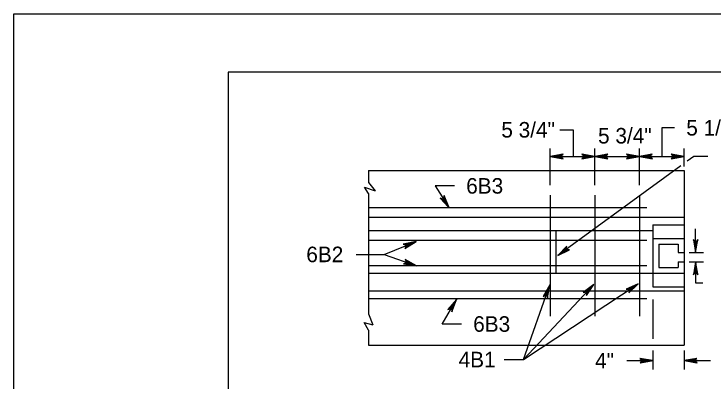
# Model space of a CAD drawing. Extents: x 499866 to 500993, y 499985 to 500645.
# Drawn here: x 499944.8 to 500124.8, y 500550.5 to 500645 of the extents above; entities that cross this region are included whole.
import ezdxf

# ---------------------------------------------------------------- set-up
doc = ezdxf.new("R2010")
doc.units = 0
for name, color, linetype in [('1', 7, 'Continuous'), ('24', 7, 'Continuous'), ('41', 7, 'Continuous'), ('5', 7, 'Continuous')]:
    doc.layers.add(name, color=color, linetype=linetype)

msp = doc.modelspace()

# ---------------------------------------------------------------- linework, layer by layer
at = {"layer": '1'}
for p, q in [((499944.83, 500645), (500993, 500645)), ((500000, 500630), (500000, 500000)), ((500990, 500630), (500000, 500630))]:
    msp.add_line(p, q, dxfattribs=at)
at = {"layer": '24'}
for points in [[(500082.83, 500608.32), (500086.18, 500607.73), (500085.38, 500608.32), (500086.16, 500608.9), (500082.83, 500608.32), (500083.05, 500608.33), (500086.09, 500607.77), (500085.32, 500608.33), (500086.03, 500608.86), (500083.17, 500608.34), (500083.29, 500608.32), (500085.88, 500607.86), (500085.3, 500608.33), (500085.9, 500608.78), (500083.34, 500608.32), (500083.45, 500608.34), (500085.72, 500607.93), (500085.28, 500608.32), (500085.73, 500608.73), (500083.77, 500608.34), (500083.96, 500608.34), (500085.55, 500608.01), (500085.24, 500608.31), (500085.57, 500608.64), (500083.99, 500608.32), (500084.17, 500608.31), (500085.37, 500608.11), (500085.14, 500608.34), (500085.39, 500608.57), (500084.34, 500608.32), (500084.51, 500608.3), (500085.22, 500608.17), (500085.11, 500608.33), (500085.3, 500608.51), (500084.59, 500608.32), (500085.06, 500608.21), (500084.99, 500608.34), (500085.2, 500608.47), (500084.71, 500608.34), (500085.02, 500608.26), (500084.89, 500608.36), (500085.04, 500608.42), (500084.89, 500608.33), (500084.97, 500608.31)], [(500094.32, 500608.32), (500090.97, 500608.91), (500091.77, 500608.32), (500090.99, 500607.74), (500094.32, 500608.32), (500094.1, 500608.31), (500091.07, 500608.87), (500091.84, 500608.31), (500091.12, 500607.78), (500093.98, 500608.3), (500093.87, 500608.32), (500091.27, 500608.78), (500091.85, 500608.31), (500091.25, 500607.86), (500093.82, 500608.32), (500093.71, 500608.3), (500091.43, 500608.71), (500091.88, 500608.32), (500091.43, 500607.91), (500093.38, 500608.3), (500093.19, 500608.3), (500091.6, 500608.63), (500091.91, 500608.33), (500091.58, 500608), (500093.16, 500608.32), (500092.98, 500608.33), (500091.79, 500608.54), (500092.02, 500608.3), (500091.77, 500608.07), (500092.82, 500608.32), (500092.65, 500608.34), (500091.93, 500608.47), (500092.05, 500608.31), (500091.85, 500608.13), (500092.56, 500608.32), (500092.09, 500608.43), (500092.16, 500608.3), (500091.95, 500608.18), (500092.44, 500608.3), (500092.14, 500608.38), (500092.26, 500608.28), (500092.12, 500608.22), (500092.26, 500608.31), (500092.19, 500608.33)], [(500094.32, 500608.32), (500097.67, 500607.73), (500096.87, 500608.32), (500097.66, 500608.9), (500094.32, 500608.32), (500094.54, 500608.33), (500097.58, 500607.77), (500096.81, 500608.33), (500097.52, 500608.86), (500094.67, 500608.34), (500094.78, 500608.32), (500097.38, 500607.86), (500096.79, 500608.33), (500097.39, 500608.78), (500094.83, 500608.32), (500094.94, 500608.34), (500097.21, 500607.93), (500096.77, 500608.32), (500097.22, 500608.73), (500095.26, 500608.34), (500095.45, 500608.34), (500097.04, 500608.01), (500096.73, 500608.31), (500097.07, 500608.64), (500095.49, 500608.32), (500095.66, 500608.31), (500096.86, 500608.11), (500096.63, 500608.34), (500096.88, 500608.57), (500095.83, 500608.32), (500096, 500608.3), (500096.72, 500608.17), (500096.6, 500608.33), (500096.79, 500608.51), (500096.08, 500608.32), (500096.55, 500608.21), (500096.49, 500608.34), (500096.69, 500608.47), (500096.2, 500608.34), (500096.51, 500608.26), (500096.38, 500608.36), (500096.53, 500608.42), (500096.38, 500608.33), (500096.46, 500608.31)], [(500105.81, 500608.32), (500102.46, 500608.91), (500103.26, 500608.32), (500102.48, 500607.74), (500105.81, 500608.32), (500105.59, 500608.31), (500102.56, 500608.87), (500103.33, 500608.31), (500102.62, 500607.78), (500105.47, 500608.3), (500105.36, 500608.32), (500102.76, 500608.78), (500103.34, 500608.31), (500102.74, 500607.86), (500105.31, 500608.32), (500105.2, 500608.3), (500102.93, 500608.71), (500103.37, 500608.32), (500102.92, 500607.91), (500104.87, 500608.3), (500104.69, 500608.3), (500103.09, 500608.63), (500103.4, 500608.33), (500103.07, 500608), (500104.65, 500608.32), (500104.47, 500608.33), (500103.28, 500608.54), (500103.51, 500608.3), (500103.26, 500608.07), (500104.31, 500608.32), (500104.14, 500608.34), (500103.42, 500608.47), (500103.54, 500608.31), (500103.34, 500608.13), (500104.05, 500608.32), (500103.58, 500608.43), (500103.65, 500608.3), (500103.45, 500608.18), (500103.93, 500608.3), (500103.63, 500608.38), (500103.76, 500608.28), (500103.61, 500608.22), (500103.75, 500608.31), (500103.68, 500608.33)], [(500105.81, 500608.32), (500109.16, 500607.73), (500108.36, 500608.32), (500109.15, 500608.9), (500105.81, 500608.32), (500106.04, 500608.33), (500109.07, 500607.77), (500108.3, 500608.33), (500109.01, 500608.86), (500106.16, 500608.34), (500106.27, 500608.32), (500108.87, 500607.86), (500108.28, 500608.33), (500108.88, 500608.78), (500106.32, 500608.32), (500106.43, 500608.34), (500108.7, 500607.93), (500108.26, 500608.32), (500108.71, 500608.73), (500106.75, 500608.34), (500106.94, 500608.34), (500108.53, 500608.01), (500108.22, 500608.31), (500108.56, 500608.64), (500106.98, 500608.32), (500107.16, 500608.31), (500108.35, 500608.11), (500108.12, 500608.34), (500108.37, 500608.57), (500107.32, 500608.32), (500107.49, 500608.3), (500108.21, 500608.17), (500108.09, 500608.33), (500108.28, 500608.51), (500107.58, 500608.32), (500108.04, 500608.21), (500107.98, 500608.34), (500108.18, 500608.47), (500107.69, 500608.34), (500108, 500608.26), (500107.87, 500608.36), (500108.02, 500608.42), (500107.87, 500608.33), (500107.95, 500608.31)], [(500117.31, 500608.32), (500113.96, 500608.91), (500114.76, 500608.32), (500113.97, 500607.74), (500117.31, 500608.32), (500117.08, 500608.31), (500114.05, 500608.87), (500114.82, 500608.31), (500114.11, 500607.78), (500116.96, 500608.3), (500116.85, 500608.32), (500114.25, 500608.78), (500114.84, 500608.31), (500114.24, 500607.86), (500116.8, 500608.32), (500116.69, 500608.3), (500114.42, 500608.71), (500114.86, 500608.32), (500114.41, 500607.91), (500116.37, 500608.3), (500116.18, 500608.3), (500114.59, 500608.63), (500114.9, 500608.33), (500114.56, 500608), (500116.14, 500608.32), (500115.96, 500608.33), (500114.77, 500608.54), (500115, 500608.3), (500114.75, 500608.07), (500115.8, 500608.32), (500115.63, 500608.34), (500114.91, 500608.47), (500115.03, 500608.31), (500114.83, 500608.13), (500115.54, 500608.32), (500115.07, 500608.43), (500115.14, 500608.3), (500114.94, 500608.18), (500115.43, 500608.3), (500115.12, 500608.38), (500115.25, 500608.28), (500115.1, 500608.22), (500115.25, 500608.31), (500115.17, 500608.33)], [(500056.82, 500595.07), (500055.54, 500598.22), (500055.46, 500597.23), (500054.55, 500597.58), (500056.82, 500595.07), (500056.7, 500595.26), (500055.55, 500598.12), (500055.49, 500597.17), (500054.66, 500597.49), (500056.63, 500595.35), (500056.58, 500595.45), (500055.58, 500597.9), (500055.5, 500597.16), (500054.79, 500597.42), (500056.55, 500595.5), (500056.48, 500595.58), (500055.61, 500597.72), (500055.52, 500597.14), (500054.93, 500597.3), (500056.31, 500595.86), (500056.21, 500596.02), (500055.63, 500597.54), (500055.54, 500597.11), (500055.08, 500597.22), (500056.2, 500596.05), (500056.12, 500596.21), (500055.65, 500597.33), (500055.58, 500597.01), (500055.25, 500597.1), (500056.02, 500596.34), (500055.94, 500596.5), (500055.68, 500597.18), (500055.6, 500596.99), (500055.35, 500597.06), (500055.88, 500596.56), (500055.73, 500597.02), (500055.65, 500596.89), (500055.44, 500597), (500055.81, 500596.65), (500055.71, 500596.95), (500055.69, 500596.79), (500055.56, 500596.88), (500055.72, 500596.81), (500055.69, 500596.88)], [(500048.32, 500586.44), (500044.99, 500585.71), (500045.96, 500585.47), (500045.46, 500584.63), (500048.32, 500586.44), (500048.11, 500586.35), (500045.1, 500585.71), (500046.02, 500585.49), (500045.56, 500584.73), (500048.01, 500586.29), (500047.9, 500586.26), (500045.32, 500585.71), (500046.04, 500585.49), (500045.65, 500584.85), (500047.85, 500586.25), (500047.75, 500586.19), (500045.5, 500585.71), (500046.05, 500585.51), (500045.79, 500584.96), (500047.45, 500586.06), (500047.28, 500585.99), (500045.68, 500585.69), (500046.08, 500585.53), (500045.9, 500585.1), (500047.24, 500586), (500047.07, 500585.94), (500045.89, 500585.67), (500046.19, 500585.55), (500046.05, 500585.24), (500046.92, 500585.87), (500046.76, 500585.82), (500046.04, 500585.67), (500046.22, 500585.57), (500046.1, 500585.33), (500046.69, 500585.77), (500046.21, 500585.69), (500046.32, 500585.6), (500046.18, 500585.4), (500046.58, 500585.71), (500046.27, 500585.66), (500046.43, 500585.62), (500046.31, 500585.51), (500046.42, 500585.65), (500046.34, 500585.64)], [(500084.81, 500582.81), (500087.86, 500584.3), (500086.87, 500584.31), (500087.16, 500585.24), (500084.81, 500582.81), (500084.98, 500582.95), (500087.76, 500584.29), (500086.81, 500584.28), (500087.08, 500585.13), (500085.07, 500583.02), (500085.17, 500583.08), (500087.55, 500584.23), (500086.8, 500584.27), (500087.02, 500584.99), (500085.22, 500583.11), (500085.3, 500583.19), (500087.37, 500584.19), (500086.78, 500584.25), (500086.91, 500584.85), (500085.56, 500583.38), (500085.71, 500583.49), (500087.19, 500584.16), (500086.76, 500584.22), (500086.83, 500584.69), (500085.75, 500583.49), (500085.9, 500583.59), (500086.98, 500584.13), (500086.66, 500584.18), (500086.73, 500584.51), (500086.02, 500583.7), (500086.17, 500583.78), (500086.83, 500584.09), (500086.64, 500584.16), (500086.69, 500584.42), (500086.23, 500583.85), (500086.68, 500584.03), (500086.55, 500584.1), (500086.64, 500584.32), (500086.32, 500583.93), (500086.61, 500584.05), (500086.45, 500584.06), (500086.53, 500584.19), (500086.47, 500584.03), (500086.54, 500584.06)], [(500120.3, 500583.58), (500120.9, 500586.93), (500120.3, 500586.13), (500119.72, 500586.91), (500120.3, 500583.58), (500120.3, 500583.8), (500120.85, 500586.83), (500120.3, 500586.06), (500119.77, 500586.77), (500120.29, 500583.92), (500120.3, 500584.03), (500120.76, 500586.63), (500120.3, 500586.05), (500119.84, 500586.65), (500120.3, 500584.08), (500120.29, 500584.19), (500120.7, 500586.46), (500120.3, 500586.02), (500119.89, 500586.47), (500120.29, 500584.52), (500120.29, 500584.71), (500120.61, 500586.3), (500120.31, 500585.99), (500119.98, 500586.32), (500120.3, 500584.74), (500120.31, 500584.92), (500120.52, 500586.11), (500120.29, 500585.88), (500120.06, 500586.13), (500120.3, 500585.08), (500120.32, 500585.25), (500120.46, 500585.97), (500120.3, 500585.85), (500120.12, 500586.05), (500120.3, 500585.34), (500120.41, 500585.81), (500120.29, 500585.74), (500120.16, 500585.94), (500120.29, 500585.46), (500120.36, 500585.76), (500120.26, 500585.63), (500120.2, 500585.78), (500120.3, 500585.64), (500120.31, 500585.71)], [(500048.45, 500580.12), (500045.49, 500581.81), (500046.05, 500580.98), (500045.11, 500580.69), (500048.45, 500580.12), (500048.23, 500580.19), (500045.56, 500581.73), (500046.1, 500580.95), (500045.25, 500580.69), (500048.12, 500580.22), (500048.02, 500580.28), (500045.73, 500581.58), (500046.12, 500580.95), (500045.4, 500580.72), (500047.97, 500580.29), (500047.86, 500580.31), (500045.86, 500581.46), (500046.14, 500580.94), (500045.58, 500580.71), (500047.56, 500580.42), (500047.38, 500580.49), (500045.99, 500581.33), (500046.18, 500580.94), (500045.75, 500580.74), (500047.35, 500580.51), (500047.19, 500580.58), (500046.13, 500581.18), (500046.27, 500580.88), (500045.96, 500580.75), (500047.03, 500580.63), (500046.88, 500580.7), (500046.24, 500581.07), (500046.3, 500580.88), (500046.06, 500580.78), (500046.79, 500580.72), (500046.38, 500580.98), (500046.4, 500580.83), (500046.17, 500580.78), (500046.67, 500580.74), (500046.41, 500580.91), (500046.49, 500580.78), (500046.33, 500580.77), (500046.5, 500580.81), (500046.44, 500580.85)], [(500120.3, 500581.18), (500119.71, 500577.83), (500120.3, 500578.63), (500120.89, 500577.85), (500120.3, 500581.18), (500120.31, 500580.96), (500119.75, 500577.93), (500120.31, 500578.7), (500120.84, 500577.99), (500120.32, 500580.84), (500120.3, 500580.73), (500119.84, 500578.13), (500120.31, 500578.71), (500120.76, 500578.11), (500120.3, 500580.68), (500120.32, 500580.57), (500119.91, 500578.29), (500120.3, 500578.74), (500120.71, 500578.29), (500120.32, 500580.24), (500120.32, 500580.05), (500119.99, 500578.46), (500120.29, 500578.77), (500120.63, 500578.44), (500120.3, 500580.02), (500120.29, 500579.84), (500120.09, 500578.65), (500120.32, 500578.88), (500120.55, 500578.63), (500120.3, 500579.68), (500120.29, 500579.51), (500120.15, 500578.79), (500120.31, 500578.91), (500120.49, 500578.71), (500120.3, 500579.42), (500120.19, 500578.95), (500120.32, 500579.02), (500120.45, 500578.81), (500120.32, 500579.3), (500120.24, 500579), (500120.34, 500579.12), (500120.4, 500578.98), (500120.31, 500579.12), (500120.29, 500579.05)], [(500082.73, 500575.23), (500081.06, 500572.26), (500081.88, 500572.82), (500082.17, 500571.89), (500082.73, 500575.23), (500082.66, 500575.01), (500081.13, 500572.33), (500081.91, 500572.88), (500082.17, 500572.03), (500082.63, 500574.9), (500082.57, 500574.8), (500081.28, 500572.5), (500081.91, 500572.89), (500082.15, 500572.18), (500082.56, 500574.75), (500082.54, 500574.64), (500081.4, 500572.63), (500081.92, 500572.92), (500082.15, 500572.36), (500082.43, 500574.33), (500082.37, 500574.15), (500081.53, 500572.76), (500081.92, 500572.95), (500082.12, 500572.53), (500082.34, 500574.13), (500082.27, 500573.96), (500081.68, 500572.9), (500081.98, 500573.04), (500082.11, 500572.73), (500082.23, 500573.8), (500082.15, 500573.65), (500081.79, 500573.02), (500081.98, 500573.08), (500082.08, 500572.83), (500082.14, 500573.56), (500081.88, 500573.16), (500082.02, 500573.18), (500082.08, 500572.94), (500082.12, 500573.45), (500081.94, 500573.18), (500082.08, 500573.27), (500082.09, 500573.11), (500082.05, 500573.28), (500082.01, 500573.21)], [(500094.06, 500575.35), (500091.34, 500573.31), (500092.32, 500573.49), (500092.21, 500572.52), (500094.06, 500575.35), (500093.92, 500575.19), (500091.44, 500573.35), (500092.37, 500573.53), (500092.27, 500572.65), (500093.84, 500575.09), (500093.75, 500575.02), (500091.64, 500573.44), (500092.38, 500573.55), (500092.31, 500572.8), (500093.72, 500574.99), (500093.66, 500574.89), (500091.81, 500573.51), (500092.39, 500573.57), (500092.38, 500572.96), (500093.44, 500574.66), (500093.31, 500574.52), (500091.98, 500573.58), (500092.41, 500573.6), (500092.43, 500573.13), (500093.27, 500574.5), (500093.14, 500574.38), (500092.17, 500573.65), (500092.5, 500573.66), (500092.5, 500573.32), (500093.04, 500574.25), (500092.91, 500574.14), (500092.32, 500573.71), (500092.52, 500573.69), (500092.51, 500573.42), (500092.86, 500574.07), (500092.46, 500573.8), (500092.6, 500573.76), (500092.55, 500573.53), (500092.79, 500573.97), (500092.53, 500573.8), (500092.69, 500573.82), (500092.63, 500573.67), (500092.66, 500573.85), (500092.6, 500573.8)], [(500105.53, 500575.48), (500102.41, 500574.13), (500103.4, 500574.08), (500103.07, 500573.16), (500105.53, 500575.48), (500105.35, 500575.36), (500102.51, 500574.15), (500103.46, 500574.11), (500103.16, 500573.28), (500105.26, 500575.28), (500105.15, 500575.23), (500102.73, 500574.19), (500103.48, 500574.12), (500103.23, 500573.41), (500105.11, 500575.21), (500105.03, 500575.13), (500102.91, 500574.22), (500103.49, 500574.14), (500103.34, 500573.55), (500104.76, 500574.95), (500104.6, 500574.85), (500103.09, 500574.25), (500103.52, 500574.17), (500103.42, 500573.7), (500104.56, 500574.84), (500104.41, 500574.75), (500103.3, 500574.27), (500103.62, 500574.2), (500103.53, 500573.87), (500104.28, 500574.65), (500104.13, 500574.58), (500103.45, 500574.3), (500103.64, 500574.23), (500103.57, 500573.97), (500104.06, 500574.51), (500103.61, 500574.35), (500103.74, 500574.28), (500103.64, 500574.06), (500103.97, 500574.44), (500103.67, 500574.33), (500103.84, 500574.32), (500103.75, 500574.19), (500103.82, 500574.34), (500103.75, 500574.32)], [(500058.76, 500571.49), (500056.55, 500568.9), (500057.46, 500569.29), (500057.57, 500568.32), (500058.76, 500571.49), (500058.65, 500571.29), (500056.63, 500568.96), (500057.5, 500569.34), (500057.6, 500568.46), (500058.6, 500571.18), (500058.53, 500571.1), (500056.81, 500569.09), (500057.51, 500569.35), (500057.6, 500568.61), (500058.5, 500571.05), (500058.46, 500570.95), (500056.95, 500569.2), (500057.52, 500569.38), (500057.64, 500568.78), (500058.29, 500570.67), (500058.2, 500570.51), (500057.11, 500569.3), (500057.53, 500569.41), (500057.65, 500568.96), (500058.17, 500570.49), (500058.07, 500570.34), (500057.29, 500569.41), (500057.6, 500569.49), (500057.67, 500569.16), (500057.99, 500570.19), (500057.89, 500570.05), (500057.41, 500569.5), (500057.61, 500569.52), (500057.67, 500569.26), (500057.86, 500569.97), (500057.53, 500569.62), (500057.67, 500569.61), (500057.68, 500569.37), (500057.82, 500569.86), (500057.6, 500569.63), (500057.75, 500569.69), (500057.73, 500569.53), (500057.72, 500569.71), (500057.67, 500569.65)], [(500109.31, 500555.74), (500105.96, 500556.33), (500106.76, 500555.74), (500105.98, 500555.16), (500109.31, 500555.74), (500109.09, 500555.74), (500106.05, 500556.29), (500106.82, 500555.73), (500106.11, 500555.2), (500108.97, 500555.72), (500108.86, 500555.74), (500106.26, 500556.2), (500106.84, 500555.73), (500106.24, 500555.28), (500108.81, 500555.74), (500108.69, 500555.72), (500106.42, 500556.13), (500106.86, 500555.74), (500106.41, 500555.33), (500108.37, 500555.72), (500108.18, 500555.72), (500106.59, 500556.05), (500106.9, 500555.75), (500106.57, 500555.42), (500108.15, 500555.74), (500107.97, 500555.75), (500106.77, 500555.96), (500107, 500555.72), (500106.75, 500555.5), (500107.81, 500555.74), (500107.64, 500555.76), (500106.92, 500555.9), (500107.04, 500555.73), (500106.84, 500555.56), (500107.55, 500555.74), (500107.08, 500555.85), (500107.15, 500555.72), (500106.94, 500555.6), (500107.43, 500555.72), (500107.12, 500555.8), (500107.25, 500555.7), (500107.1, 500555.64), (500107.25, 500555.73), (500107.17, 500555.75)], [(500117.31, 500555.74), (500120.66, 500555.15), (500119.85, 500555.74), (500120.64, 500556.32), (500117.31, 500555.74), (500117.53, 500555.75), (500120.56, 500555.19), (500119.79, 500555.75), (500120.5, 500556.28), (500117.65, 500555.76), (500117.76, 500555.74), (500120.36, 500555.28), (500119.77, 500555.75), (500120.37, 500556.2), (500117.81, 500555.74), (500117.92, 500555.76), (500120.19, 500555.35), (500119.75, 500555.74), (500120.2, 500556.15), (500118.25, 500555.76), (500118.43, 500555.76), (500120.02, 500555.43), (500119.72, 500555.73), (500120.05, 500556.06), (500118.47, 500555.74), (500118.65, 500555.73), (500119.84, 500555.53), (500119.61, 500555.76), (500119.86, 500555.99), (500118.81, 500555.74), (500118.98, 500555.72), (500119.7, 500555.59), (500119.58, 500555.75), (500119.78, 500555.93), (500119.07, 500555.74), (500119.54, 500555.63), (500119.47, 500555.76), (500119.67, 500555.89), (500119.19, 500555.76), (500119.49, 500555.68), (500119.36, 500555.78), (500119.51, 500555.84), (500119.36, 500555.75), (500119.44, 500555.73)]]:
    msp.add_lwpolyline(points, dxfattribs=at)
at = {"layer": '41'}
msp.add_lwpolyline([(499944.83, 500645), (500993, 500645), (500993, 499985), (499944.83, 499985)], close=True, dxfattribs=at)
at = {"layer": '5'}
for p, q in [((500082.83, 500600.93), (500082.83, 500610.32)), ((500094.32, 500600.93), (500094.32, 500610.32)), ((500105.81, 500600.93), (500105.81, 500610.32)), ((500117.31, 500605.71), (500117.31, 500610.32)), ((500082.83, 500608.32), (500094.32, 500608.32)), ((500094.32, 500608.32), (500105.81, 500608.32)), ((500105.81, 500608.32), (500117.31, 500608.32)), ((500116.53, 500605.93), (500084.81, 500582.81)), ((500036.09, 500604.7), (500117.31, 500604.7)), ((500036.09, 500604.7), (500036.09, 500601.6)), ((500117.31, 500604.7), (500117.31, 500559.74)), ((500036.09, 500601.6), (500037.84, 500599.5)), ((500036.09, 500598.78), (500035.07, 500600.42)), ((500035.07, 500600.42), (500037.84, 500599.5)), ((500036.09, 500598.78), (500036.09, 500567.81)), ((500082.83, 500598.31), (500082.83, 500567.22)), ((500094.32, 500598.31), (500094.32, 500567.22)), ((500105.81, 500598.31), (500105.81, 500567.22)), ((500036.09, 500595.21), (500107.77, 500595.21)), ((500036.09, 500592.71), (500117.31, 500592.71)), ((500109.31, 500590.71), (500117.31, 500590.71)), ((500109.31, 500590.71), (500109.31, 500578.22)), ((500036.09, 500589.22), (500109.31, 500589.22)), ((500084.33, 500589.22), (500084.33, 500578.22)), ((500120.3, 500583.58), (500120.3, 500589.67)), ((500109.31, 500587.22), (500117.31, 500587.22)), ((500036.09, 500586.72), (500107.77, 500586.72)), ((500040.14, 500583.09), (500048.32, 500586.44)), ((500110.81, 500585.72), (500115.81, 500585.72)), ((500110.81, 500585.72), (500110.81, 500579.72)), ((500115.81, 500585.72), (500115.81, 500583.58)), ((500115.81, 500583.58), (500117.31, 500583.58)), ((500118.61, 500583.58), (500122.3, 500583.58)), ((500036.09, 500580.22), (500107.77, 500580.22)), ((500115.81, 500581.18), (500115.81, 500579.72)), ((500115.81, 500581.18), (500117.31, 500581.18)), ((500118.61, 500581.18), (500122.3, 500581.18)), ((500036.09, 500578.22), (500109.31, 500578.22)), ((500109.31, 500578.22), (500117.31, 500578.22)), ((500109.31, 500578.22), (500109.31, 500574.73)), ((500110.81, 500579.72), (500115.81, 500579.72)), ((500075.99, 500556.02), (500094.06, 500575.35)), ((500075.99, 500556.02), (500082.73, 500575.23)), ((500109.31, 500574.73), (500117.31, 500574.73)), ((500036.09, 500573.73), (500117.31, 500573.73)), ((500036.09, 500571.73), (500107.77, 500571.73)), ((500109.31, 500571.49), (500109.31, 500561.31)), ((500036.09, 500567.81), (500037.17, 500564.95)), ((500036.09, 500563.59), (500034.99, 500565.53)), ((500034.99, 500565.53), (500037.17, 500564.95)), ((500036.09, 500563.59), (500036.09, 500559.74)), ((500036.09, 500559.74), (500117.31, 500559.74)), ((500109.31, 500558.34), (500109.31, 500553.45)), ((500117.31, 500558.34), (500117.31, 500553.45)), ((500102.56, 500555.74), (500109.31, 500555.74)), ((500117.31, 500555.74), (500124.09, 500555.74))]:
    msp.add_line(p, q, dxfattribs=at)
for points in [[(500085.36, 500615.18), (500088.81, 500615.18), (500088.81, 500608.32)], [(500114.89, 500615.69), (500111.56, 500615.69), (500111.56, 500608.32)], [(500123.42, 500608.32), (500119.8, 500608.32), (500118.16, 500607.12)], [(500058.24, 500600.74), (500053.24, 500600.74), (500056.82, 500595.07)], [(500032.89, 500583.09), (500040.14, 500583.09), (500048.45, 500580.12)], [(500120.3, 500581.18), (500120.3, 500575.8), (500122.11, 500575.8)], [(500071, 500556.02), (500075.99, 500556.02), (500105.53, 500575.48)], [(500060.04, 500565.17), (500055.05, 500565.17), (500058.76, 500571.49)]]:
    msp.add_lwpolyline(points, dxfattribs=at)

# ---------------------------------------------------------------- texts
for s, p in [('5 1/2"', (500117.89, 500613.69)), ('5 3/4"', (500070.28, 500613.18)), ('5 3/4"', (500095.18, 500611.65)), ('6B3', (500061.24, 500598.74)), ('6B2', (500020.08, 500581.09)), ('6B3', (500063.04, 500563.17)), ('4B1', (500059.29, 500554.02)), ('4"', (500094.42, 500553.74))]:
    msp.add_text(s, height=4, dxfattribs=at).set_placement(p)

doc.saveas('drawing.dxf')
